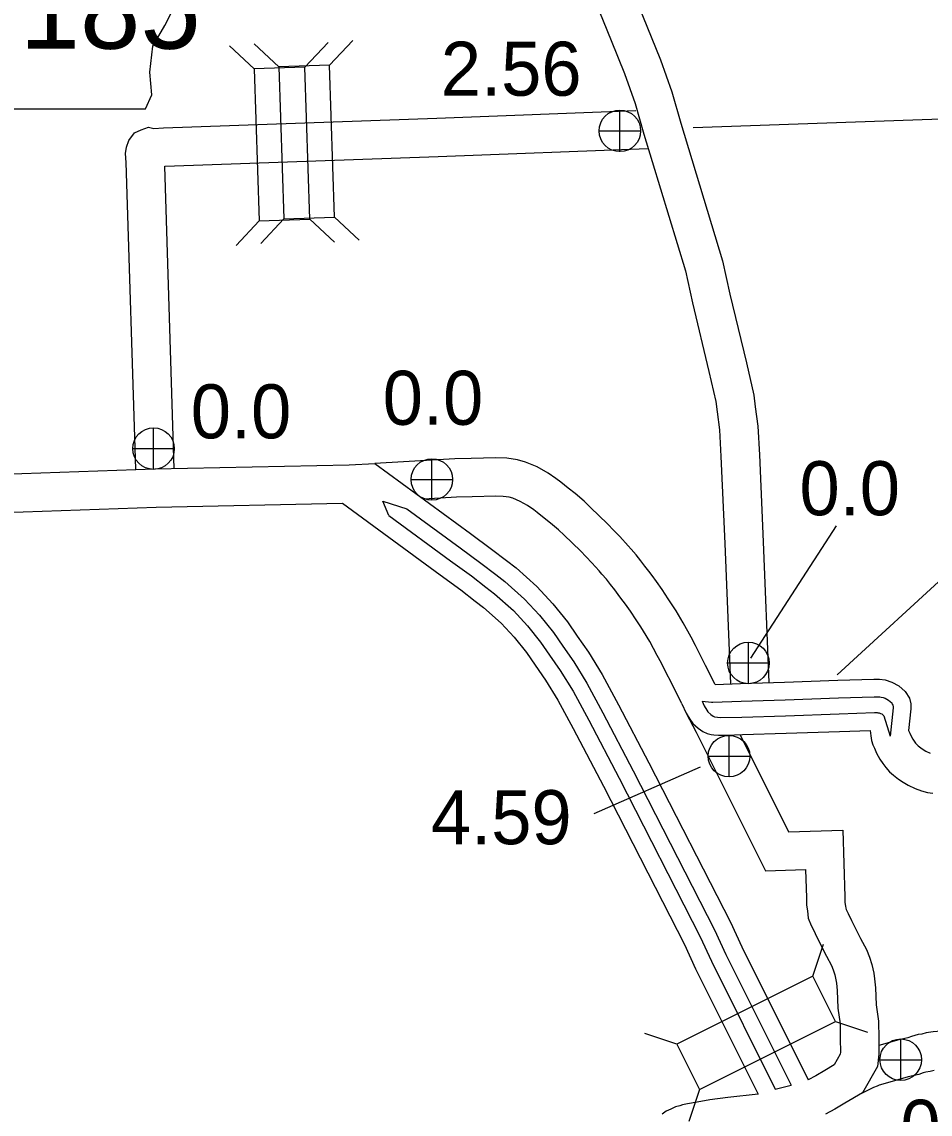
# Model space of a CAD drawing. Extents: x -939622 to -934222, y 1383701 to 1385301.
# Drawn here: x -935731.43 to -935710.14, y 1384054.1 to 1384079.72 of the extents above; entities that cross this region are included whole.
import ezdxf

# ---------------------------------------------------------------- set-up
doc = ezdxf.new("R2010")
doc.units = 0
for name, color, linetype in [('Level 10', 7, 'Continuous'), ('Level 15', 7, 'Continuous'), ('Level 20', 7, 'Continuous'), ('Level 21', 7, 'Continuous'), ('Level 22', 7, 'Continuous'), ('Level 25', 7, 'Continuous'), ('Level 26', 7, 'Continuous'), ('Level 8', 7, 'Continuous')]:
    doc.layers.add(name, color=color, linetype=linetype)

msp = doc.modelspace()

# ---------------------------------------------------------------- linework, layer by layer
at = {"layer": 'Level 10'}
for points in [[(-935717.165, 1384080.564), (-935716.781, 1384079.618), (-935716.461, 1384078.826), (-935716.2, 1384078.077), (-935715.989, 1384077.342), (-935715.007, 1384074.11), (-935714.836, 1384073.333), (-935714.45, 1384071.725), (-935714.277, 1384070.967), (-935714.243, 1384070.693), (-935714.18, 1384070.234), (-935714.145, 1384069.564), (-935714.056, 1384067.524), (-935713.924, 1384064.221)], [(-935717.99, 1384080.202), (-935717.615, 1384079.28), (-935717.304, 1384078.509), (-935717.058, 1384077.804), (-935716.853, 1384077.087), (-935715.879, 1384073.882), (-935715.714, 1384073.131), (-935715.326, 1384071.52), (-935715.165, 1384070.811), (-935715.135, 1384070.576), (-935715.076, 1384070.149), (-935715.044, 1384069.521), (-935714.956, 1384067.486), (-935714.823, 1384064.19)], [(-935728.76, 1384069.225), (-935728.987, 1384076.423), (-935729, 1384076.631), (-935728.978, 1384076.783), (-935728.925, 1384076.933), (-935728.794, 1384077.114), (-935728.639, 1384077.184), (-935728.467, 1384077.245), (-935728.34, 1384077.22), (-935728.113, 1384077.235), (-935721.708, 1384077.456), (-935717.039, 1384077.641)], [(-935727.86, 1384069.239), (-935728.084, 1384076.335), (-935728.069, 1384076.336), (-935721.675, 1384076.557), (-935716.761, 1384076.751)], [(-935715.86, 1384063.506), (-935715.628, 1384063.063), (-935713.998, 1384059.809), (-935713.062, 1384059.836), (-935713.041, 1384059.171), (-935713.037, 1384058.999), (-935713.02, 1384058.869), (-935712.999, 1384058.695), (-935712.927, 1384058.528), (-935712.877, 1384058.424), (-935712.796, 1384058.251), (-935712.571, 1384057.807), (-935712.455, 1384057.59), (-935712.414, 1384057.482), (-935712.376, 1384057.37), (-935712.349, 1384057.249), (-935712.339, 1384057.174), (-935712.324, 1384057.002), (-935712.303, 1384056.585), (-935712.254, 1384056.218), (-935712.248, 1384055.866), (-935712.245, 1384055.553), (-935712.251, 1384055.504), (-935712.394, 1384055.257)], [(-935714.592, 1384062.999), (-935713.459, 1384060.725), (-935712.192, 1384060.762), (-935712.141, 1384059.196), (-935712.138, 1384059.067), (-935712.127, 1384058.981), (-935712.121, 1384058.934), (-935712.107, 1384058.899), (-935712.064, 1384058.809), (-935711.987, 1384058.646), (-935711.773, 1384058.223), (-935711.634, 1384057.963), (-935711.567, 1384057.786), (-935711.509, 1384057.614), (-935711.462, 1384057.407), (-935711.445, 1384057.272), (-935711.426, 1384057.066), (-935711.406, 1384056.666), (-935711.356, 1384056.285), (-935711.348, 1384055.878), (-935711.345, 1384055.505), (-935711.378, 1384055.215), (-935711.731, 1384054.604)], [(-935706.719, 1384056.258), (-935707.021, 1384056.218), (-935707.147, 1384056.234), (-935707.322, 1384056.266), (-935707.496, 1384056.276), (-935707.668, 1384056.287), (-935707.819, 1384056.277), (-935707.976, 1384056.273), (-935708.166, 1384056.252), (-935708.357, 1384056.228), (-935708.841, 1384056.158), (-935709.111, 1384056.112), (-935709.881, 1384056.043), (-935710.074, 1384056.029), (-935710.235, 1384056.009), (-935710.333, 1384055.98), (-935710.421, 1384055.968), (-935710.582, 1384055.925), (-935710.667, 1384055.892), (-935710.875, 1384055.847), (-935711.344, 1384055.711)], [(-935712.394, 1384055.257), (-935712.612, 1384055.127), (-935712.819, 1384054.998), (-935712.999, 1384054.905)], [(-935710.05, 1384055.125), (-935710.142, 1384055.098), (-935710.244, 1384055.084), (-935710.302, 1384055.068), (-935710.406, 1384055.027), (-935710.655, 1384054.974), (-935711.251, 1384054.801), (-935711.333, 1384054.778), (-935711.384, 1384054.758), (-935711.473, 1384054.729), (-935711.844, 1384054.537), (-935711.85, 1384054.533)], [(-935714.174, 1384054.571), (-935714.88, 1384054.491), (-935715.305, 1384054.435), (-935715.6, 1384054.379), (-935715.826, 1384054.339), (-935715.949, 1384054.317), (-935716.01, 1384054.297), (-935716.11, 1384054.269), (-935716.221, 1384054.219), (-935716.327, 1384054.167), (-935716.426, 1384054.097)], [(-935711.731, 1384054.604), (-935712.144, 1384054.358), (-935712.374, 1384054.215), (-935712.595, 1384054.101)]]:
    msp.add_lwpolyline(points, dxfattribs=at)
at = {"layer": 'Level 15'}
for points in [[(-935715.179, 1384064.176), (-935715.406, 1384064.625), (-935715.531, 1384064.871), (-935715.641, 1384065.09), (-935715.747, 1384065.286), (-935715.931, 1384065.627), (-935716.097, 1384065.906), (-935716.172, 1384066.023), (-935716.28, 1384066.184), (-935716.421, 1384066.404), (-935716.555, 1384066.59), (-935716.661, 1384066.733), (-935716.736, 1384066.837), (-935716.83, 1384066.954), (-935716.924, 1384067.074), (-935717.036, 1384067.218), (-935717.152, 1384067.35), (-935717.221, 1384067.433), (-935717.412, 1384067.645), (-935717.553, 1384067.793), (-935717.702, 1384067.948), (-935718.099, 1384068.329), (-935718.253, 1384068.474), (-935718.466, 1384068.656), (-935718.624, 1384068.782), (-935718.799, 1384068.924), (-935718.912, 1384069.007), (-935719.097, 1384069.137), (-935719.355, 1384069.282), (-935719.629, 1384069.395), (-935719.815, 1384069.448), (-935720.065, 1384069.488), (-935720.321, 1384069.495), (-935720.899, 1384069.481), (-935721.283, 1384069.471), (-935721.678, 1384069.445), (-935723.157, 1384069.36)], [(-935739.622, 1384068.836), (-935736.339, 1384068.956), (-935728.312, 1384069.238)], [(-935728.306, 1384069.238), (-935723.756, 1384069.333)], [(-935723.756, 1384069.333), (-935723.157, 1384069.36)], [(-935723.157, 1384069.36), (-935720.917, 1384067.716), (-935720.421, 1384067.353), (-935720.073, 1384067.082), (-935719.849, 1384066.913), (-935719.359, 1384066.473), (-935718.983, 1384066.072), (-935718.641, 1384065.644), (-935718.412, 1384065.311), (-935718.15, 1384064.933), (-935717.831, 1384064.413), (-935717.444, 1384063.704)], [(-935728.287, 1384068.338), (-935723.917, 1384068.43)], [(-935723.917, 1384068.43), (-935721.627, 1384066.749), (-935721.145, 1384066.395), (-935720.804, 1384066.13), (-935720.613, 1384065.985), (-935720.199, 1384065.614), (-935719.891, 1384065.286), (-935719.605, 1384064.929), (-935719.4, 1384064.63), (-935719.156, 1384064.277), (-935718.869, 1384063.811), (-935718.508, 1384063.149)], [(-935722.831, 1384068.144), (-935722.969, 1384068.478), (-935722.41, 1384068.3)], [(-935715.96, 1384063.726), (-935716.208, 1384064.218), (-935716.335, 1384064.466), (-935716.439, 1384064.675), (-935716.538, 1384064.858), (-935716.714, 1384065.183), (-935716.862, 1384065.432), (-935716.925, 1384065.529), (-935717.033, 1384065.691), (-935717.165, 1384065.897), (-935717.282, 1384066.059), (-935717.388, 1384066.202), (-935717.452, 1384066.291), (-935717.536, 1384066.395), (-935717.633, 1384066.52), (-935717.73, 1384066.644), (-935717.838, 1384066.766), (-935717.903, 1384066.845), (-935718.072, 1384067.033), (-935718.204, 1384067.171), (-935718.338, 1384067.312), (-935718.72, 1384067.677), (-935718.855, 1384067.805), (-935719.039, 1384067.962), (-935719.189, 1384068.081), (-935719.35, 1384068.212), (-935719.435, 1384068.275), (-935719.576, 1384068.373), (-935719.749, 1384068.471), (-935719.926, 1384068.544), (-935720.01, 1384068.568), (-935720.148, 1384068.59), (-935720.323, 1384068.595), (-935720.877, 1384068.582), (-935721.241, 1384068.572), (-935721.623, 1384068.546), (-935722.017, 1384068.524)], [(-935763.589, 1384067.017), (-935755.992, 1384067.287), (-935748.213, 1384067.681), (-935745.868, 1384067.761), (-935745.773, 1384067.748), (-935745.672, 1384067.711), (-935745.404, 1384067.622), (-935745.133, 1384067.58), (-935744.912, 1384067.52), (-935744.675, 1384067.506), (-935744.458, 1384067.505), (-935744.221, 1384067.509), (-935743.971, 1384067.542), (-935743.756, 1384067.598), (-935743.54, 1384067.662), (-935743.296, 1384067.715), (-935743.118, 1384067.753), (-935742.859, 1384067.77), (-935742.135, 1384067.843), (-935736.307, 1384068.057), (-935728.28, 1384068.339)], [(-935722.831, 1384068.144), (-935721.383, 1384067.081), (-935720.896, 1384066.724), (-935720.553, 1384066.457), (-935720.35, 1384066.304), (-935719.91, 1384065.91), (-935719.579, 1384065.556), (-935719.274, 1384065.174), (-935719.06, 1384064.864), (-935718.81, 1384064.502), (-935718.512, 1384064.018), (-935718.142, 1384063.34)], [(-935722.41, 1384068.3), (-935721.161, 1384067.384), (-935720.67, 1384067.024), (-935720.324, 1384066.755), (-935720.112, 1384066.594), (-935719.648, 1384066.178), (-935719.295, 1384065.802), (-935718.972, 1384065.398), (-935718.751, 1384065.077), (-935718.496, 1384064.707), (-935718.188, 1384064.206), (-935717.81, 1384063.513)], [(-935715.179, 1384064.176), (-935714.587, 1384064.2), (-935713.555, 1384064.234), (-935712.304, 1384064.277), (-935711.461, 1384064.305), (-935711.329, 1384064.305), (-935711.195, 1384064.285), (-935711.036, 1384064.236), (-935710.876, 1384064.149), (-935710.727, 1384064.015), (-935710.623, 1384063.856), (-935710.592, 1384063.721), (-935710.595, 1384063.603), (-935710.647, 1384063.1)], [(-935715.487, 1384063.785), (-935715.263, 1384063.763), (-935715.236, 1384063.761), (-935714.572, 1384063.788), (-935713.541, 1384063.821), (-935712.29, 1384063.865), (-935711.454, 1384063.892), (-935711.359, 1384063.892), (-935711.324, 1384063.889), (-935711.287, 1384063.882), (-935711.241, 1384063.87), (-935711.197, 1384063.854), (-935711.16, 1384063.837), (-935711.116, 1384063.81), (-935711.078, 1384063.782), (-935711.043, 1384063.744), (-935711.029, 1384063.719), (-935711.018, 1384063.692), (-935711.01, 1384063.661), (-935711.007, 1384063.628), (-935711.075, 1384062.969)], [(-935715.487, 1384063.785), (-935715.437, 1384063.674), (-935715.379, 1384063.573), (-935715.35, 1384063.533), (-935715.282, 1384063.471), (-935715.224, 1384063.432), (-935715.2, 1384063.421), (-935715.056, 1384063.403), (-935714.558, 1384063.413), (-935713.529, 1384063.446), (-935712.277, 1384063.49), (-935711.448, 1384063.517), (-935711.386, 1384063.517), (-935711.37, 1384063.515), (-935711.335, 1384063.509), (-935711.32, 1384063.506), (-935711.306, 1384063.501), (-935711.276, 1384063.488), (-935711.25, 1384063.467), (-935711.228, 1384063.441), (-935711.075, 1384062.969)], [(-935717.81, 1384063.513), (-935717.1, 1384062.155), (-935715.193, 1384058.42), (-935714.931, 1384057.847), (-935713.398, 1384054.779)], [(-935717.444, 1384063.704), (-935716.734, 1384062.344), (-935714.822, 1384058.6), (-935714.559, 1384058.025), (-935712.999, 1384054.905)], [(-935715.96, 1384063.726), (-935715.86, 1384063.506), (-935715.778, 1384063.362), (-935715.706, 1384063.266), (-935715.583, 1384063.154), (-935715.467, 1384063.075), (-935715.371, 1384063.031), (-935715.276, 1384063.007), (-935715.211, 1384063), (-935715.102, 1384062.99), (-935714.924, 1384062.986), (-935714.543, 1384063.001), (-935713.515, 1384063.034), (-935712.263, 1384063.078), (-935711.551, 1384063.101)], [(-935718.142, 1384063.34), (-935717.434, 1384061.983), (-935715.531, 1384058.257), (-935715.27, 1384057.685), (-935713.771, 1384054.687), (-935713.398, 1384054.779)], [(-935718.508, 1384063.149), (-935717.8, 1384061.794), (-935715.902, 1384058.078), (-935715.642, 1384057.507), (-935714.174, 1384054.571)], [(-935711.551, 1384063.101), (-935711.535, 1384062.975), (-935711.515, 1384062.866), (-935711.483, 1384062.766), (-935711.448, 1384062.685), (-935711.401, 1384062.57), (-935711.319, 1384062.427), (-935711.251, 1384062.323), (-935711.18, 1384062.231), (-935711.095, 1384062.133), (-935711.004, 1384062.053), (-935710.886, 1384061.959), (-935710.774, 1384061.885), (-935710.658, 1384061.819), (-935710.495, 1384061.741), (-935710.348, 1384061.684), (-935710.205, 1384061.647), (-935710.078, 1384061.628)], [(-935710.647, 1384063.1), (-935710.619, 1384063.036), (-935710.59, 1384062.965), (-935710.551, 1384062.897), (-935710.517, 1384062.845), (-935710.485, 1384062.803), (-935710.454, 1384062.767), (-935710.425, 1384062.742), (-935710.358, 1384062.689), (-935710.303, 1384062.653), (-935710.241, 1384062.617), (-935710.138, 1384062.568)]]:
    msp.add_lwpolyline(points, dxfattribs=at)
at = {"layer": 'Level 20'}
for p, q in [((-935725.983, 1384078.615), (-935726.561, 1384079.156)), ((-935725.406, 1384078.662), (-935725.984, 1384079.204)), ((-935724.795, 1384078.653), (-935724.254, 1384079.231)), ((-935724.219, 1384078.701), (-935723.677, 1384079.279)), ((-935725.867, 1384075.053), (-935726.408, 1384074.475)), ((-935725.29, 1384075.1), (-935725.832, 1384074.522)), ((-935724.68, 1384075.091), (-935724.102, 1384074.55)), ((-935724.103, 1384075.139), (-935723.525, 1384074.597)), ((-935712.892, 1384057.335), (-935712.642, 1384058.086)), ((-935712.361, 1384056.272), (-935711.61, 1384056.022)), ((-935716.08, 1384055.741), (-935716.832, 1384055.991)), ((-935715.549, 1384054.678), (-935715.799, 1384053.927))]:
    msp.add_line(p, q, dxfattribs=at)
for points in [[(-935725.983, 1384078.615), (-935725.867, 1384075.053), (-935724.68, 1384075.091), (-935724.795, 1384078.653)], [(-935725.406, 1384078.662), (-935725.29, 1384075.1), (-935724.103, 1384075.139), (-935724.219, 1384078.701)], [(-935712.892, 1384057.335), (-935716.08, 1384055.741), (-935715.549, 1384054.678), (-935712.361, 1384056.272)]]:
    msp.add_lwpolyline(points, close=True, dxfattribs=at)
at = {"layer": 'Level 21'}
msp.add_lwpolyline([(-935732.444, 1384082.45), (-935732.215, 1384080.927), (-935732.317, 1384078.618), (-935732.114, 1384078.491), (-935731.733, 1384078.491), (-935731.733, 1384077.679), (-935728.536, 1384077.679), (-935728.383, 1384078.009), (-935728.434, 1384078.542), (-935728.358, 1384079.151), (-935728.079, 1384079.633), (-935727.901, 1384079.988), (-935727.648, 1384080.369), (-935727.495, 1384080.775), (-935727.368, 1384081.105), (-935727.14, 1384081.384), (-935727.089, 1384081.562), (-935727.191, 1384081.689), (-935727.977, 1384081.689), (-935727.8, 1384082.044), (-935727.774, 1384082.272), (-935727.88, 1384082.448)], close=True, dxfattribs=at)
at = {"layer": 'Level 22'}
msp.add_line((-935707.068, 1384069.226), (-935712.324, 1384064.405), dxfattribs=at)
at = {"layer": 'Level 25'}
for p, q in [((-935714.343, 1384064.793), (-935712.338, 1384067.897)), ((-935718.016, 1384061.149), (-935715.528, 1384062.249))]:
    msp.add_line(p, q, dxfattribs=at)
at = {"layer": 'Level 26'}
for p, q in [((-935717.414, 1384076.674), (-935717.414, 1384077.649)), ((-935717.901, 1384077.162), (-935716.926, 1384077.162)), ((-935728.345, 1384069.223), (-935728.345, 1384070.198)), ((-935728.832, 1384069.71), (-935727.857, 1384069.71)), ((-935721.821, 1384068.498), (-935721.821, 1384069.473)), ((-935722.308, 1384068.985), (-935721.333, 1384068.985)), ((-935714.402, 1384064.196), (-935714.402, 1384065.171)), ((-935714.889, 1384064.683), (-935713.914, 1384064.683)), ((-935714.856, 1384062.01), (-935714.856, 1384062.985)), ((-935715.344, 1384062.497), (-935714.369, 1384062.497)), ((-935710.831, 1384054.89), (-935710.831, 1384055.865)), ((-935711.318, 1384055.378), (-935710.343, 1384055.378))]:
    msp.add_line(p, q, dxfattribs=at)
for centre in [(-935717.414, 1384077.162), (-935728.345, 1384069.71), (-935721.821, 1384068.985), (-935714.402, 1384064.683), (-935714.856, 1384062.497), (-935710.831, 1384055.378)]:
    msp.add_circle(centre, 0.487, dxfattribs=at)
at = {"layer": 'Level 8'}
msp.add_lwpolyline([(-935715.693, 1384077.238), (-935708.759, 1384077.487)], dxfattribs=at)

# ---------------------------------------------------------------- texts
at = {"layer": 'Level 21'}
msp.add_text('185', height=1.9008, dxfattribs=at).set_placement((-935731.482, 1384079.089))
at = {"layer": 'Level 25'}
for s, p in [('2.56', (-935721.611, 1384077.986)), ('0.0', (-935722.973, 1384070.268)), ('0.0', (-935727.472, 1384069.95)), ('0.0', (-935713.204, 1384068.147)), ('4.59', (-935721.843, 1384060.431)), ('0.0', (-935710.838, 1384053.171))]:
    msp.add_text(s, height=1.2672, dxfattribs=at).set_placement(p)

doc.saveas('drawing.dxf')
